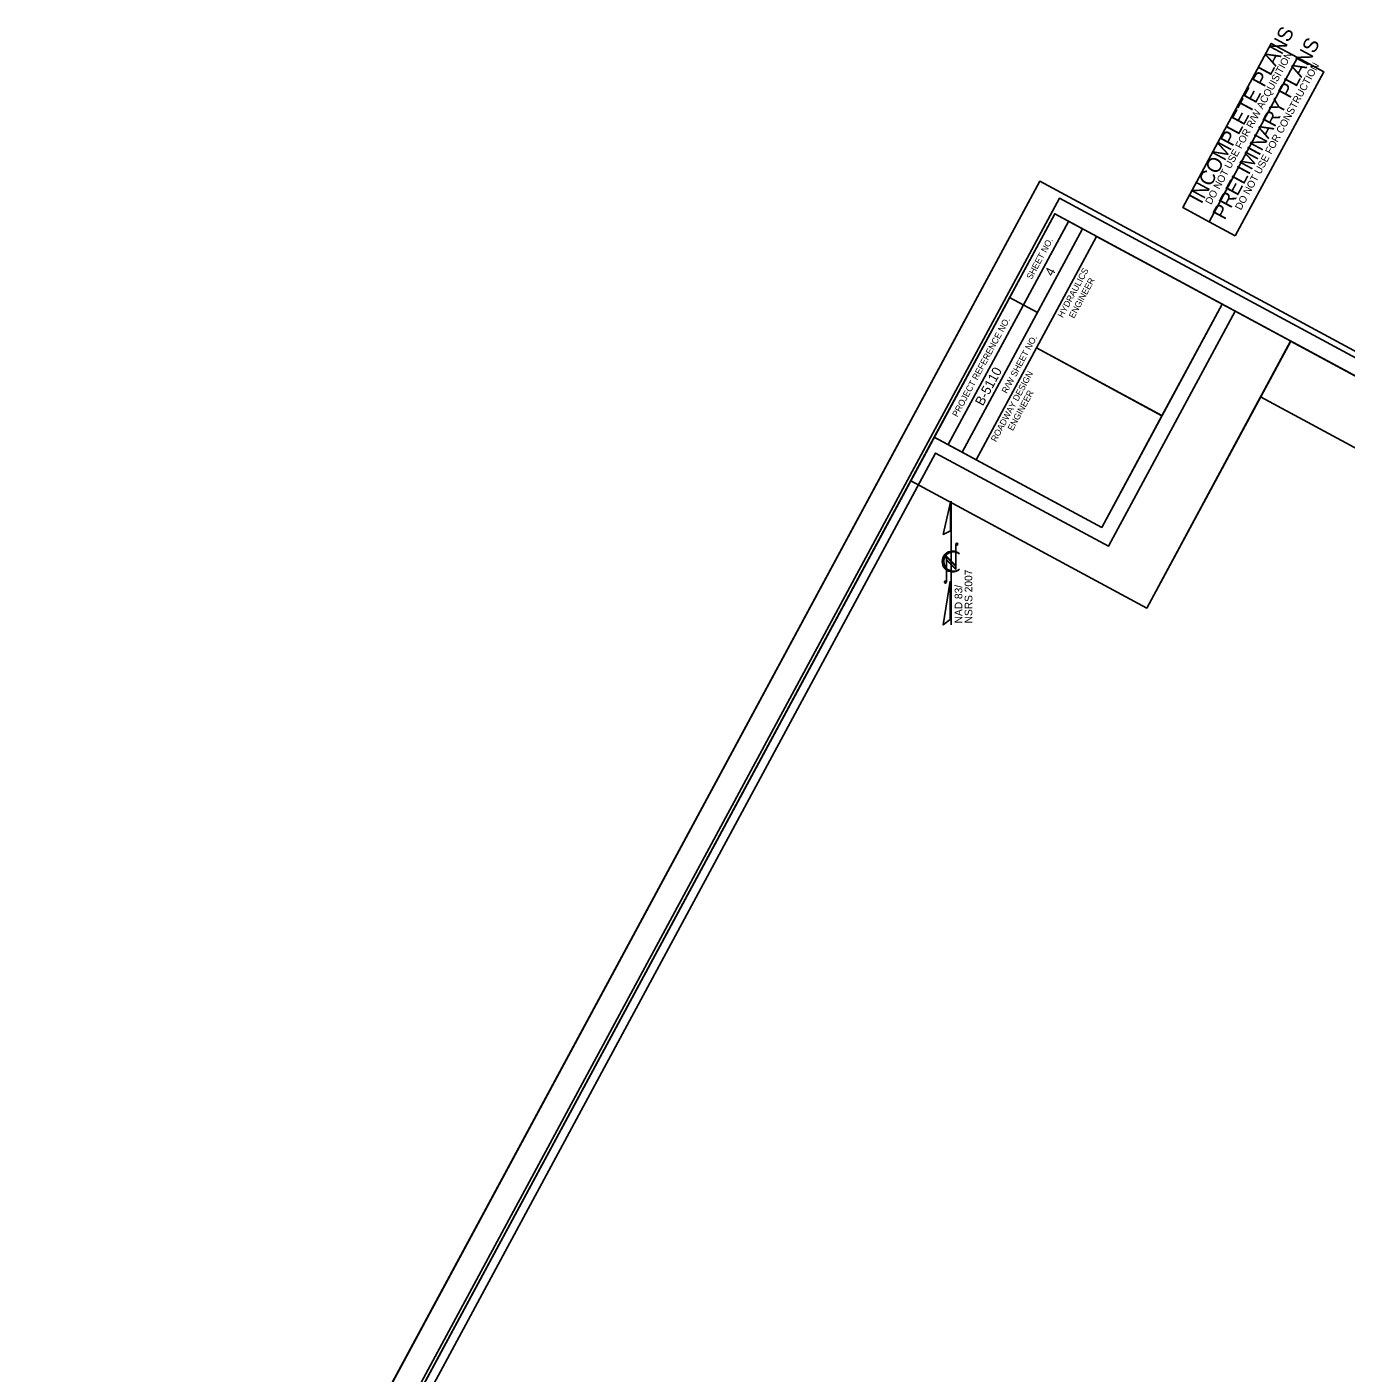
# Model space of a CAD drawing. Extents: x 1376633 to 1377691, y 762405 to 763679.
# Drawn here: x 1376633 to 1377258, y 763042 to 763679 of the extents above; entities that cross this region are included whole.
import ezdxf

# ---------------------------------------------------------------- set-up
doc = ezdxf.new("R2010")
doc.units = 0
for name, color, linetype in [('Sheet Clip Boundary CELL', 7, 'Continuous'), ('Sheet Cutting Line CELL', 7, 'Continuous'), ('Sheet Data Field CELL', 7, 'Continuous'), ('Sheet Layout Plan Border', 7, 'Continuous'), ('Sheet North Arrow CELL', 7, 'Continuous'), ('Sheet Plan CELL', 7, 'Continuous'), ('Sheet Plan Layout CELL', 7, 'Continuous'), ('Sheet Plot Border Inside CELL', 7, 'Continuous'), ('Sheet Plot Border Outside CELL', 7, 'Continuous'), ('Sheet Sticker Incomplete CELL', 7, 'Continuous'), ('Sheet Sticker Preliminary CELL', 7, 'Continuous')]:
    doc.layers.add(name, color=color, linetype=linetype)

msp = doc.modelspace()

# ---------------------------------------------------------------- linework, layer by layer
at = {"layer": 'Sheet Clip Boundary CELL'}
msp.add_lwpolyline([(1377242.74, 762501.71), (1377605.3, 763174.23), (1377567.4, 763194.66), (1377631.93, 763314.35), (1377205.29, 763544.36), (1377145.3, 763433.08), (1377063.51, 763477.17), (1376696.41, 762796.24)], close=True, dxfattribs=at)
at = {"layer": 'Sheet Cutting Line CELL'}
msp.add_line((1377112.79, 763605.82), (1376633.46, 762716.69), dxfattribs=at)
at = {"layer": 'Sheet Layout Plan Border'}
msp.add_lwpolyline([(1377261.52, 762525.66), (1377660.14, 763265.06), (1377217.29, 763503.81), (1377163.4, 763403.85), (1377051.71, 763464.07), (1376706.97, 762824.63)], close=True, dxfattribs=at)
at = {"layer": 'Sheet North Arrow CELL'}
for p, q in [((1377070.9, 763395.92), (1377070.9, 763454.42)), ((1377073.1, 763434.06), (1377073.1, 763422.05)), ((1377073.1, 763423.93), (1377068.63, 763428.4)), ((1377068.63, 763428.4), (1377068.63, 763416.2)), ((1377073.1, 763423.49), (1377068.63, 763427.96)), ((1377068.63, 763427.96), (1377068.63, 763426.86)), ((1377073.1, 763422.39), (1377068.63, 763426.86)), ((1377068.63, 763426.86), (1377073.1, 763422.39)), ((1377073.1, 763422.05), (1377068.63, 763426.53)), ((1377074.76, 763429.59), (1377074.82, 763429.54)), ((1377073.1, 763422.39), (1377073.1, 763423.49))]:
    msp.add_line(p, q, dxfattribs=at)
for points in [[(1377070.49, 763453.91), (1377067.15, 763438.71), (1377070.49, 763440.41)], [(1377070.42, 763416.53), (1377067.11, 763395.92), (1377070.42, 763398.53)]]:
    msp.add_lwpolyline(points, close=True, dxfattribs=at)
for centre in [(1377073.58, 763434.05), (1377068.15, 763416.18)]:
    msp.add_circle(centre, 0.477, dxfattribs=at)
for centre, radius, start, end in [((1377071.52, 763425.9), 4.91, 47.84002, 312.39406), ((1377071.99, 763425.9), 4.61, 53.09504, 308.62871)]:
    msp.add_arc(centre, radius, start, end, dxfattribs=at)
at = {"layer": 'Sheet Plan CELL'}
for p, q in [((1377069.49, 763481.2), (1377126.46, 763586.85)), ((1377076.11, 763477.64), (1377133.06, 763583.3)), ((1377076.11, 763477.64), (1377133.06, 763583.3)), ((1377098.5, 763550.79), (1377111.72, 763543.69)), ((1377111.2, 763526.93), (1377170.6, 763494.91)), ((1377076.11, 763477.64), (1377082.71, 763474.08))]:
    msp.add_line(p, q, dxfattribs=at)
for points in [[(1377119.84, 763590.45), (1376692.74, 762798.22), (1377247.28, 762499.26), (1377674.38, 763291.47)], [(1377062.86, 763484.78), (1377119.84, 763590.45), (1377133.06, 763583.3), (1377076.11, 763477.64)], [(1377111.2, 763526.93), (1377139.66, 763579.74), (1377199.08, 763547.71), (1377170.62, 763494.89)], [(1377247.28, 762499.26), (1376692.74, 762798.2), (1377062.86, 763484.78), (1377142.12, 763442.06), (1377199.08, 763547.71), (1377674.38, 763291.47)], [(1377082.71, 763474.08), (1377111.2, 763526.93), (1377170.62, 763494.89), (1377142.12, 763442.06)]]:
    msp.add_lwpolyline(points, close=True, dxfattribs=at)
at = {"layer": 'Sheet Plan Layout CELL'}
for points in [[(1377163.4, 763403.85), (1377231.53, 763530.22), (1377119.84, 763590.45), (1377051.71, 763464.07)], [(1376692.74, 762798.2), (1377247.28, 762499.26), (1377674.37, 763291.46), (1377231.52, 763530.21), (1377163.4, 763403.85), (1377051.71, 763464.07)]]:
    msp.add_lwpolyline(points, close=True, dxfattribs=at)
at = {"layer": 'Sheet Plot Border Inside CELL'}
msp.add_lwpolyline([(1377204.91, 762417.48), (1377679.25, 763297.35), (1377122.08, 763597.74), (1376647.72, 762717.87)], close=True, dxfattribs=at)
at = {"layer": 'Sheet Plot Border Outside CELL'}
msp.add_lwpolyline([(1377211.77, 762404.92), (1377691.11, 763294.04), (1377112.79, 763605.82), (1376633.46, 762716.69)], close=True, dxfattribs=at)
at = {"layer": 'Sheet Sticker Incomplete CELL'}
msp.add_lwpolyline([(1377192.91, 763586.67), (1377180.5, 763593.36), (1377222.35, 763671), (1377234.76, 763664.31)], close=True, dxfattribs=at)
at = {"layer": 'Sheet Sticker Preliminary CELL'}
msp.add_lwpolyline([(1377205.32, 763579.98), (1377192.91, 763586.67), (1377234.76, 763664.31), (1377247.17, 763657.62)], close=True, dxfattribs=at)

# ---------------------------------------------------------------- texts
at = {"layer": 'Sheet Data Field CELL'}
for s, p in [(' 4 ', (1377118.07, 763559.03)), (' B-5110  ', (1377085.06, 763497.72))]:
    msp.add_text(s, height=4.5, rotation=61.67024, dxfattribs=at).set_placement(p)
at = {"layer": 'Sheet North Arrow CELL'}
for s, p in [('NSRS 2007', (1377080.85, 763396.62)), ('NAD 83/', (1377076.13, 763396.62))]:
    msp.add_text(s, height=3.6, rotation=90, dxfattribs=at).set_placement(p)
at = {"layer": 'Sheet Plan CELL'}
for s, height, p in [('SHEET NO.', 3, (1377108.92, 763559.04)), ('HYDRAULICS', 3, (1377123.71, 763540.94)), ('ENGINEER', 3, (1377128.99, 763540.66)), ('PROJECT REFERENCE NO.', 3.0001, (1377073.79, 763494.02)), ('R/W SHEET NO.', 3.0001, (1377097.2, 763505.13)), ('ROADWAY DESIGN', 3.0001, (1377092.08, 763482.24)), ('ENGINEER', 3, (1377100.05, 763487.48))]:
    msp.add_text(s, height=height, rotation=61.67024, dxfattribs=at).set_placement(p)
at = {"layer": 'Sheet Sticker Incomplete CELL'}
for s, height, p in [('INCOMPLETE PLANS', 6.912, (1377189.28, 763594.73)), ('DO NOT USE FOR R/W ACQUISITION', 3.456, (1377193.87, 763594.47))]:
    msp.add_text(s, height=height, rotation=61.67024, dxfattribs=at).set_placement(p)
at = {"layer": 'Sheet Sticker Preliminary CELL'}
for s, height, p in [('PRELIMINARY PLANS', 6.912, (1377200.23, 763587.16)), ('DO NOT USE FOR CONSTRUCTION', 3.456, (1377208.02, 763591.88))]:
    msp.add_text(s, height=height, rotation=61.67024, dxfattribs=at).set_placement(p)

doc.saveas('drawing.dxf')
